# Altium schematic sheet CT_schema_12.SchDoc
size 147 x 119 mm
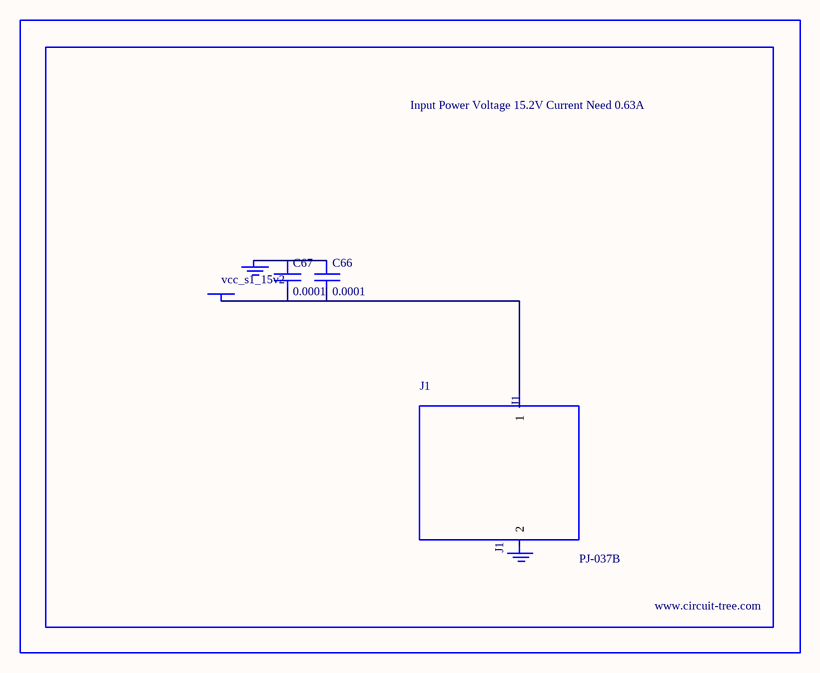
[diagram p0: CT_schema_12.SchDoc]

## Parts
BORDER11  (no value)
C66  0.0001  [EXV-9H]
C67  0.0001  [EXV-9H]
GND_INSTANCE_11_0  (no value)
GND_INSTANCE_11_1  (no value)
J1  PJ-037B  [PJ-037B_PACKAGE]
POWER_INSTANCE_11_0  vcc_s1_15v2

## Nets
NetC66_1: C66.1 C67.1 GND_INSTANCE_11_0.0(GND)
NetC66_2: C66.2 C67.2 J1.1 POWER_INSTANCE_11_0.0(PWR)

Not connected (* = marked no-connect by the designer): GND_INSTANCE_11_1 0(GND); J1 2

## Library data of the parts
BORDER11 = BORDER_PAGE11
C66 C67 = EDK107M035A9HAA
GND_INSTANCE_11_0 GND_INSTANCE_11_1 = GND
POWER_INSTANCE_11_0 = PWR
